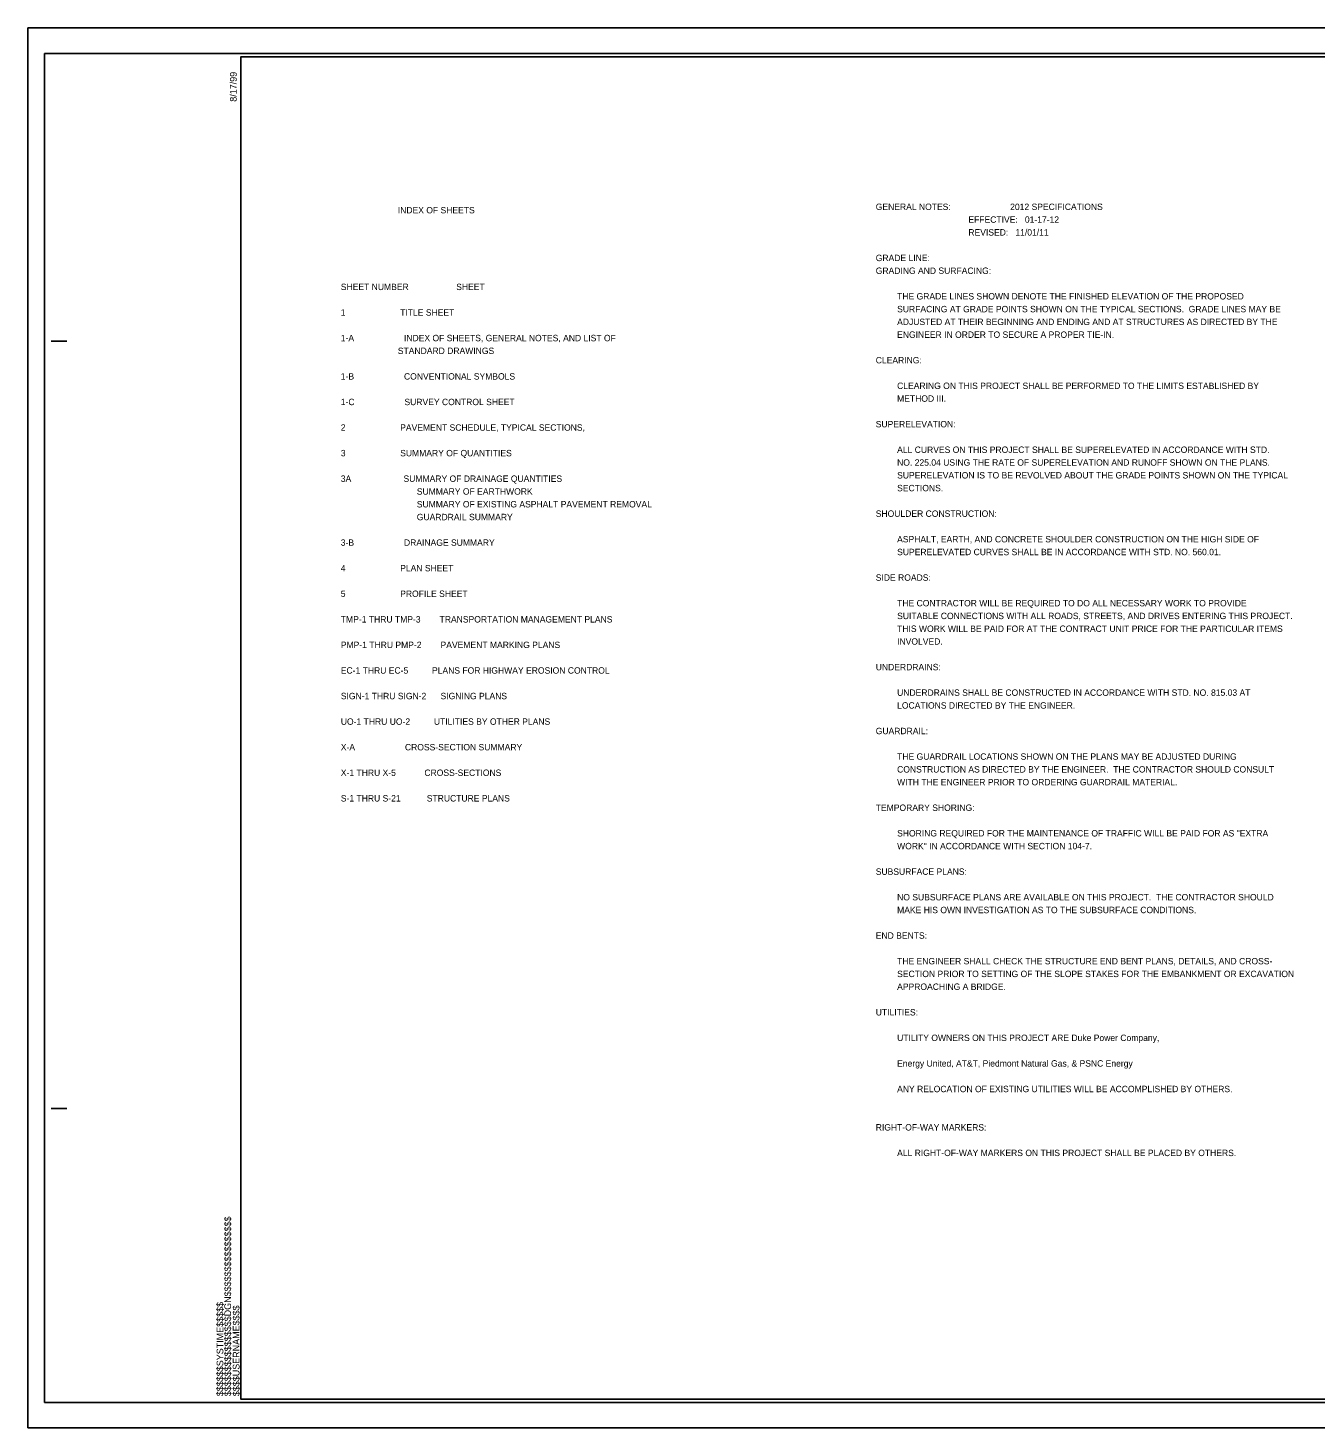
# Model space of a CAD drawing. Extents: x 573853.4 to 573887.1, y -53299.2 to -53277.3.
# Drawn here: x 573853.39 to 573873.53, y -53299.24 to -53277.34 of the extents above; entities that cross this region are included whole.
import ezdxf

# ---------------------------------------------------------------- set-up
doc = ezdxf.new("R2010")
doc.units = 0
for name, color, linetype in [('Prop Dimension Text', 7, 'Continuous'), ('Sheet Cutting Line CELL', 7, 'Continuous'), ('Sheet Plan CELL', 7, 'Continuous'), ('Sheet Plot Border Inside CELL', 7, 'Continuous'), ('Sheet Plot Border Outside CELL', 7, 'Continuous')]:
    doc.layers.add(name, color=color, linetype=linetype)

msp = doc.modelspace()

# ---------------------------------------------------------------- linework, layer by layer
at = {"layer": 'Sheet Cutting Line CELL'}
for p, q in [((573887.06, -53277.34), (573853.39, -53277.34)), ((573853.39, -53277.34), (573853.39, -53299.24)), ((573853.39, -53299.24), (573887.06, -53299.24))]:
    msp.add_line(p, q, dxfattribs=at)
at = {"layer": 'Sheet Plan CELL'}
for p, q in [((573856.72, -53277.79), (573856.72, -53277.79)), ((573853.75, -53282.24), (573854, -53282.24)), ((573853.75, -53294.24), (573854, -53294.24)), ((573856.72, -53298.79), (573856.72, -53298.79))]:
    msp.add_line(p, q, dxfattribs=at)
msp.add_lwpolyline([(573886.72, -53277.79), (573856.72, -53277.79), (573856.72, -53298.79), (573886.72, -53298.79)], close=True, dxfattribs=at)
at = {"layer": 'Sheet Plot Border Inside CELL'}
msp.add_lwpolyline([(573853.65, -53298.84), (573886.97, -53298.84), (573886.97, -53277.74), (573853.65, -53277.74)], close=True, dxfattribs=at)
at = {"layer": 'Sheet Plot Border Outside CELL'}
msp.add_lwpolyline([(573853.39, -53299.24), (573887.06, -53299.24), (573887.06, -53277.34), (573853.39, -53277.34)], close=True, dxfattribs=at)

# ---------------------------------------------------------------- texts
at = {"layer": 'Prop Dimension Text'}
for s, p in [('                        INDEX OF SHEETS ', (573858.284, -53280.24)), ('GENERAL NOTES:                         2012 SPECIFICATIONS', (573866.653, -53280.187)), ('                                       EFFECTIVE:   01-17-12', (573866.653, -53280.387)), ('                                       REVISED:   11/01/11', (573866.653, -53280.587)), ('GRADE LINE:  ', (573866.653, -53280.987)), ('GRADING AND SURFACING:  ', (573866.653, -53281.187)), ('SHEET NUMBER                    SHEET   ', (573858.284, -53281.44)), ('         THE GRADE LINES SHOWN DENOTE THE FINISHED ELEVATION OF THE PROPOSED ', (573866.653, -53281.587)), ('1                       TITLE SHEET', (573858.284, -53281.84)), ('         SURFACING AT GRADE POINTS SHOWN ON THE TYPICAL SECTIONS.  GRADE LINES MAY BE ', (573866.653, -53281.787)), ('         ADJUSTED AT THEIR BEGINNING AND ENDING AND AT STRUCTURES AS DIRECTED BY THE ', (573866.653, -53281.987)), ('1-A                     INDEX OF SHEETS, GENERAL NOTES, AND LIST OF ', (573858.284, -53282.24)), ('         ENGINEER IN ORDER TO SECURE A PROPER TIE-IN.  ', (573866.653, -53282.187)), ('                        STANDARD DRAWINGS', (573858.284, -53282.44)), ('CLEARING:  ', (573866.653, -53282.587)), ('1-B                     CONVENTIONAL SYMBOLS', (573858.284, -53282.84)), ('         CLEARING ON THIS PROJECT SHALL BE PERFORMED TO THE LIMITS ESTABLISHED BY ', (573866.653, -53282.987)), ('         METHOD III.', (573866.653, -53283.187)), ('1-C                     SURVEY CONTROL SHEET', (573858.284, -53283.24)), ('2                       PAVEMENT SCHEDULE, TYPICAL SECTIONS, ', (573858.284, -53283.64)), ('SUPERELEVATION:  ', (573866.653, -53283.587)), ('3                       SUMMARY OF QUANTITIES ', (573858.284, -53284.04)), ('         ALL CURVES ON THIS PROJECT SHALL BE SUPERELEVATED IN ACCORDANCE WITH STD. ', (573866.653, -53283.987)), ('         NO. 225.04 USING THE RATE OF SUPERELEVATION AND RUNOFF SHOWN ON THE PLANS.', (573866.653, -53284.187)), ('3A                      SUMMARY OF DRAINAGE QUANTITIES ', (573858.284, -53284.44)), ('         SUPERELEVATION IS TO BE REVOLVED ABOUT THE GRADE POINTS SHOWN ON THE TYPICAL ', (573866.653, -53284.387)), ('                                SUMMARY OF EARTHWORK ', (573858.284, -53284.64)), ('         SECTIONS.  ', (573866.653, -53284.587)), ('                                SUMMARY OF EXISTING ASPHALT PAVEMENT REMOVAL', (573858.284, -53284.84)), ('SHOULDER CONSTRUCTION:  ', (573866.653, -53284.987)), ('                                GUARDRAIL SUMMARY ', (573858.284, -53285.04)), ('         ASPHALT, EARTH, AND CONCRETE SHOULDER CONSTRUCTION ON THE HIGH SIDE OF', (573866.653, -53285.387)), ('3-B                     DRAINAGE SUMMARY', (573858.284, -53285.44)), ('         SUPERELEVATED CURVES SHALL BE IN ACCORDANCE WITH STD. NO. 560.01.', (573866.653, -53285.587)), ('4                       PLAN SHEET', (573858.284, -53285.84)), ('SIDE ROADS:  ', (573866.653, -53285.987)), ('5                       PROFILE SHEET  ', (573858.284, -53286.24)), ('         THE CONTRACTOR WILL BE REQUIRED TO DO ALL NECESSARY WORK TO PROVIDE ', (573866.653, -53286.387)), ('TMP-1 THRU TMP-3        TRANSPORTATION MANAGEMENT PLANS', (573858.284, -53286.64)), ('         SUITABLE CONNECTIONS WITH ALL ROADS, STREETS, AND DRIVES ENTERING THIS PROJECT.  ', (573866.653, -53286.587)), ('         THIS WORK WILL BE PAID FOR AT THE CONTRACT UNIT PRICE FOR THE PARTICULAR ITEMS ', (573866.653, -53286.787)), ('PMP-1 THRU PMP-2        PAVEMENT MARKING PLANS', (573858.284, -53287.04)), ('         INVOLVED.  ', (573866.653, -53286.987)), ('UNDERDRAINS:  ', (573866.653, -53287.387)), ('EC-1 THRU EC-5          PLANS FOR HIGHWAY EROSION CONTROL', (573858.284, -53287.44)), ('         UNDERDRAINS SHALL BE CONSTRUCTED IN ACCORDANCE WITH STD. NO. 815.03 AT ', (573866.653, -53287.787)), ('SIGN-1 THRU SIGN-2      SIGNING PLANS', (573858.284, -53287.84)), ('         LOCATIONS DIRECTED BY THE ENGINEER.  ', (573866.653, -53287.987)), ('UO-1 THRU UO-2          UTILITIES BY OTHER PLANS', (573858.284, -53288.24)), ('GUARDRAIL:  ', (573866.653, -53288.387)), ('X-A                     CROSS-SECTION SUMMARY', (573858.284, -53288.64)), ('         THE GUARDRAIL LOCATIONS SHOWN ON THE PLANS MAY BE ADJUSTED DURING ', (573866.653, -53288.787)), ('X-1 THRU X-5            CROSS-SECTIONS', (573858.284, -53289.04)), ('         CONSTRUCTION AS DIRECTED BY THE ENGINEER.  THE CONTRACTOR SHOULD CONSULT', (573866.653, -53288.987)), ('         WITH THE ENGINEER PRIOR TO ORDERING GUARDRAIL MATERIAL.', (573866.653, -53289.187)), ('S-1 THRU S-21           STRUCTURE PLANS', (573858.284, -53289.44)), ('TEMPORARY SHORING:  ', (573866.653, -53289.587)), ('         SHORING REQUIRED FOR THE MAINTENANCE OF TRAFFIC WILL BE PAID FOR AS "EXTRA ', (573866.653, -53289.987)), ('         WORK" IN ACCORDANCE WITH SECTION 104-7.  ', (573866.653, -53290.187)), ('SUBSURFACE PLANS:  ', (573866.653, -53290.587)), ('         NO SUBSURFACE PLANS ARE AVAILABLE ON THIS PROJECT.  THE CONTRACTOR SHOULD ', (573866.653, -53290.987)), ('         MAKE HIS OWN INVESTIGATION AS TO THE SUBSURFACE CONDITIONS.  ', (573866.653, -53291.187)), ('END BENTS:  ', (573866.653, -53291.587)), ('         THE ENGINEER SHALL CHECK THE STRUCTURE END BENT PLANS, DETAILS, AND CROSS-', (573866.653, -53291.987)), ('         SECTION PRIOR TO SETTING OF THE SLOPE STAKES FOR THE EMBANKMENT OR EXCAVATION ', (573866.653, -53292.187)), ('         APPROACHING A BRIDGE.  ', (573866.653, -53292.387)), ('UTILITIES:  ', (573866.653, -53292.787)), ('         UTILITY OWNERS ON THIS PROJECT ARE Duke Power Company,', (573866.653, -53293.187)), ('         Energy United, AT&T, Piedmont Natural Gas, & PSNC Energy', (573866.653, -53293.587)), ('         ANY RELOCATION OF EXISTING UTILITIES WILL BE ACCOMPLISHED BY OTHERS.  ', (573866.653, -53293.987)), ('RIGHT-OF-WAY MARKERS:  ', (573866.653, -53294.587)), ('         ALL RIGHT-OF-WAY MARKERS ON THIS PROJECT SHALL BE PLACED BY OTHERS.  ', (573866.653, -53294.987))]:
    msp.add_text(s, height=0.1, dxfattribs=at).set_placement(p)
at = {"layer": 'Sheet Plan CELL'}
for s, p in [('8/17/99', (573856.655, -53278.494)), ('$$$$$$$$$$$$$$$$DGN$$$$$$$$$$$$$$$$', (573856.567, -53298.743)), ('$$$$$$SYSTIME$$$$$', (573856.446, -53298.743)), ('$$$$USERNAME$$$$', (573856.699, -53298.743))]:
    msp.add_text(s, height=0.105, rotation=90, dxfattribs=at).set_placement(p)

doc.saveas('drawing.dxf')
